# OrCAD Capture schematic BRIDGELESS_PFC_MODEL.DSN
size A
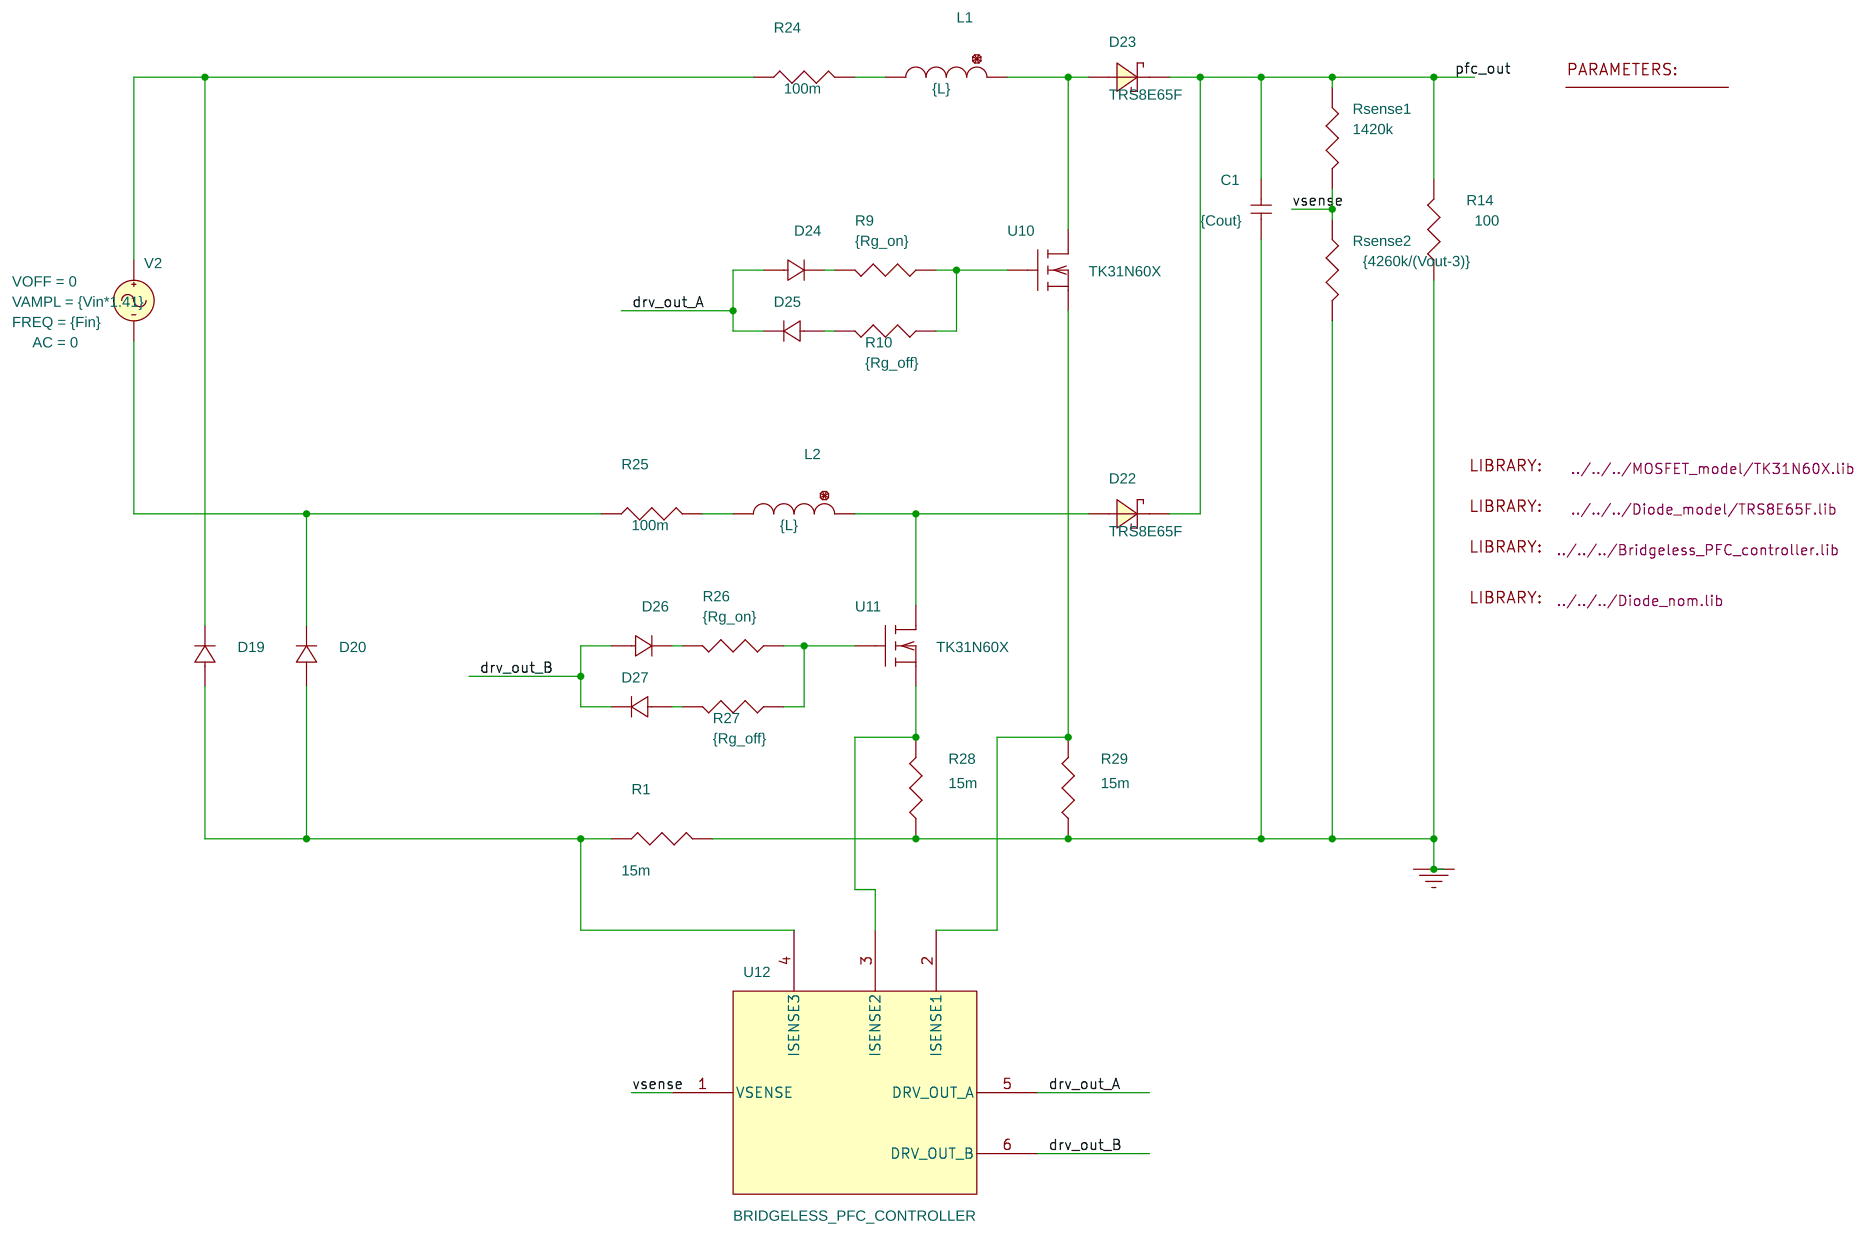
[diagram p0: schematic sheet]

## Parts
1  PARAM
C1  {Cout}  [RAD/CK05]
D19  Dbreak
D20  Dbreak
D22  TRS8E65F
D23  TRS8E65F
D24  Diode_nom
D25  Diode_nom
D26  Diode_nom
D27  Diode_nom
L1  {L}  [DISC/.350x.175/LS.200x.100/.034]
L2  {L}  [DISC/.350x.175/LS.200x.100/.034]
LIB1  LIB
LIB2  LIB
LIB3  LIB
LIB4  LIB
R1  15m
R9  {Rg_on}
R10  {Rg_off}
R14  100
R24  100m
R25  100m
R26  {Rg_on}
R27  {Rg_off}
R28  15m
R29  15m
Rsense1  1420k
Rsense2  {4260k/(Vout-3)}
U10  TK31N60X
U11  TK31N60X
U12  BRIDGELESS_PFC_CONTROLLER
V2  VSIN

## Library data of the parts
1 = PARAM: Cout: 1600u; Fc: 65k; Fin: 60; L: 130u; Rdrv_off: 0.5; Rdrv_on: 5; Rg_off: 10; Rg_on: 10; Vdrv_H: 12; Vin: 230; Vout: 400
C1 = C
D19 D20 = Dbreak
D22 D23 = TRS8E65F
D24-D27 = Diode_nom
L1 L2 = L
LIB1 = LIB: FILENAME: ../../../MOSFET_model/TK31N60X.lib
LIB2 = LIB: FILENAME: ../../../Diode_model/TRS8E65F.lib
LIB3 = LIB: FILENAME: ../../../Bridgeless_PFC_controller.lib
LIB4 = LIB: FILENAME: ../../../Diode_nom.lib
R1 R9 R10 R14 R24-R29 Rsense1 Rsense2 = R
U10 U11 = TK31N60X
U12 = BRIDGELESS_PFC_CONTROLLER
V2 = VSIN: AC: 0; FREQ: {Fin}; VAMPL: {Vin*1.41}; VOFF: 0

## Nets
0: C1.1 R1.2 R14.1 R28.1 R29.1 Rsense2.2
drv_out_A: D24.0(1) D25.1(2) U12.5(DRV_OUT_A)
drv_out_B: D26.0(1) D27.1(2) U12.6(DRV_OUT_B)
pfc_out: C1.2 D22.2 D23.2 R14.2 Rsense1.1
vsense: Rsense1.2 Rsense2.1 U12.1(VSENSE)
N1982192: D19.1(2) R24.1 V2.1(+)
N1982210: L1.2 R24.2
N1982214: D23.1 L1.1 U10.2(d)
N1982430: R9.1 R10.1 U10.1(g)
N1982594: D20.1(2) R25.1 V2.2(-)
N1982676: L2.2 R25.2
N1982680: D22.1 L2.1 U11.2(d)
N1982814: R26.1 R27.1 U11.1(g)
N1982828: D19.0(1) D20.0(1) R1.1 U12.4(ISENSE3)
N2047113: R28.2 U11.0(s) U12.3(ISENSE2)
N2047199: R29.2 U10.0(s) U12.2(ISENSE1)
N2049672: D24.1(2) R9.2
N2049735: D25.0(1) R10.2
N2049933: D26.1(2) R26.2
N2049937: D27.0(1) R27.2
